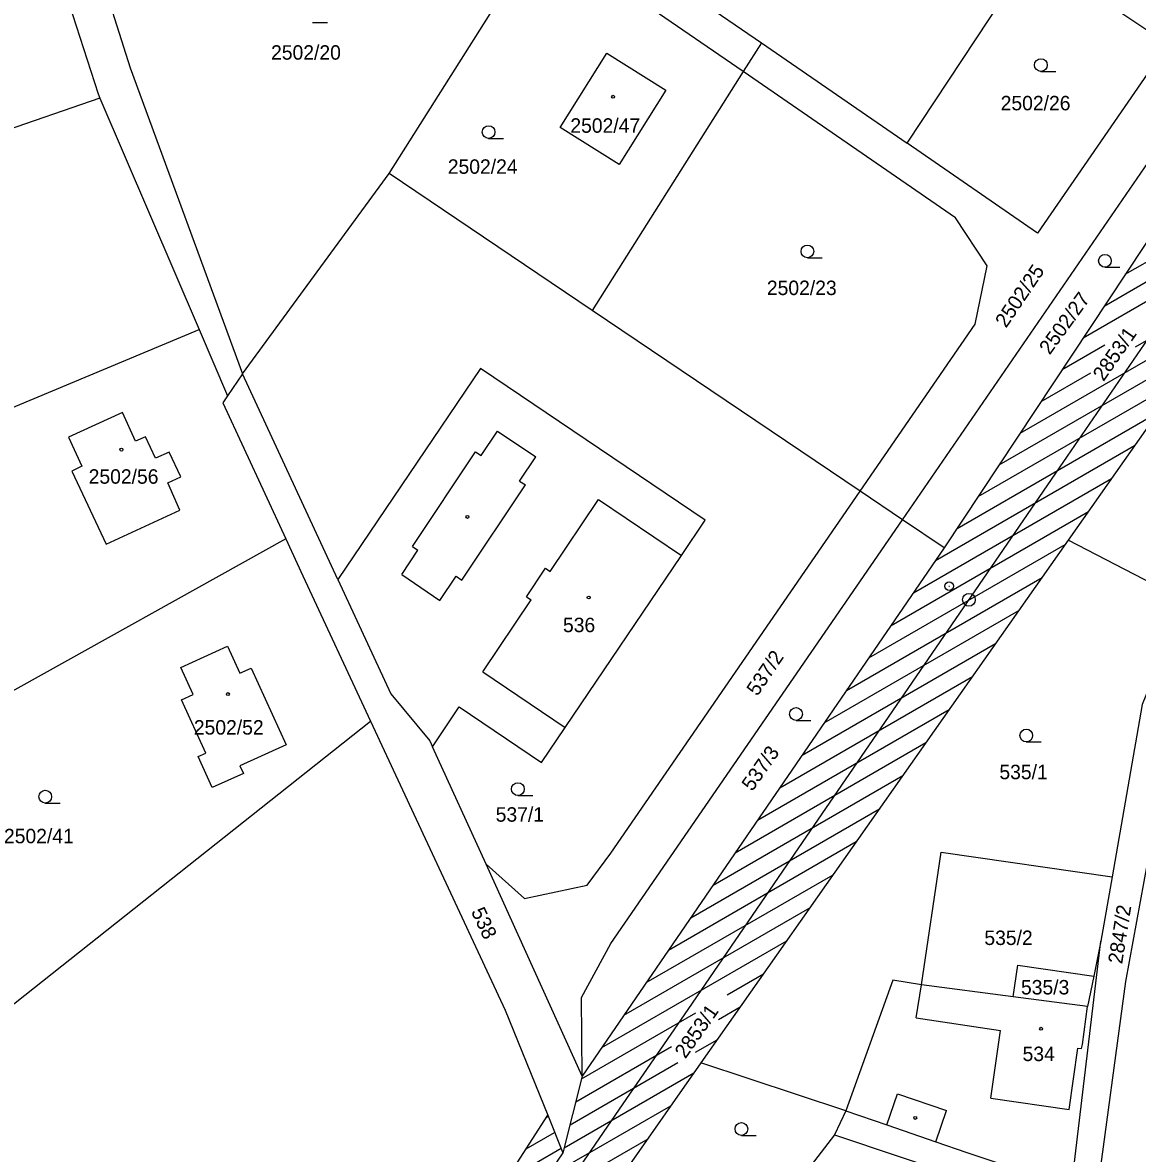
# Model space of a CAD drawing. Extents: x -558500 to -557517, y -1073973 to -1073051.
# Drawn here: x -558300.8 to -558169.6, y -1073540.5 to -1073407.4 of the extents above; entities that cross this region are included whole.
import ezdxf

# ---------------------------------------------------------------- set-up
doc = ezdxf.new("R2010")
doc.units = 0
for name, color, linetype in [('Hranice parcel', 7, 'Continuous'), ('Kolej', 7, 'Continuous'), ('Návěst místo trati', 7, 'Continuous'), ('Parcelní čísla', 7, 'Continuous'), ('Svazek obcí údolí Desné', 7, 'Continuous'), ('Vnitřní kresba', 7, 'Continuous'), ('Vrstva 1', 7, 'Continuous'), ('Značky budov', 7, 'Continuous'), ('Značky kultur', 7, 'Continuous')]:
    doc.layers.add(name, color=color, linetype=linetype)

msp = doc.modelspace()

# ---------------------------------------------------------------- linework, layer by layer
at = {"layer": 'Hranice parcel'}
for p, q in [((-558294.64, -1073392.22), (-558288.18, -1073412.71)), ((-558237.63, -1073393.44), (-558213.88, -1073409.79)), ((-558257.7, -1073425.14), (-558239.77, -1073396.82)), ((-558216.02, -1073413.17), (-558239.77, -1073396.82)), ((-558196.71, -1073421.6), (-558181.99, -1073399.3)), ((-558166.05, -1073409.92), (-558177.33, -1073402.38)), ((-558213.88, -1073409.79), (-558216.02, -1073413.17)), ((-558213.88, -1073409.79), (-558196.71, -1073421.6)), ((-558288.18, -1073412.71), (-558274.97, -1073448.74)), ((-558216.02, -1073413.17), (-558233.8, -1073441.26)), ((-558197.28, -1073465.89), (-558161.06, -1073413.25)), ((-558291.74, -1073416.28), (-558326.19, -1073428.15)), ((-558291.74, -1073416.28), (-558280.07, -1073443.5)), ((-558274.97, -1073448.74), (-558257.7, -1073425.14)), ((-558233.8, -1073441.26), (-558257.7, -1073425.14)), ((-558202.26, -1073462.53), (-558233.8, -1073441.26)), ((-558351.92, -1073473.58), (-558280.07, -1073443.5)), ((-558280.07, -1073443.5), (-558276.72, -1073451.31)), ((-558274.97, -1073448.74), (-558276.72, -1073451.31)), ((-558263.73, -1073472.95), (-558274.97, -1073448.74)), ((-558197.28, -1073465.89), (-558202.26, -1073462.53)), ((-558192.36, -1073469.21), (-558197.28, -1073465.89)), ((-558269.87, -1073468.15), (-558339.52, -1073506.95)), ((-558164.08, -1073475.42), (-558177.75, -1073468.29)), ((-558325.69, -1073541.72), (-558259.89, -1073489.61)), ((-558246.29, -1073506.44), (-558252.58, -1073492.61)), ((-558234.96, -1073531.36), (-558246.29, -1073506.44)), ((-558172.6, -1073507.93), (-558173.92, -1073515.47)), ((-558177.37, -1073544.49), (-558173.92, -1073515.47)), ((-558173.92, -1073515.47), (-558174.76, -1073519.59)), ((-558184.24, -1073522.04), (-558195.03, -1073520.62)), ((-558234.96, -1073531.36), (-558235.03, -1073522.1)), ((-558203.93, -1073535.45), (-558220.99, -1073529.81))]:
    msp.add_line(p, q, dxfattribs=at)
for points in [[(-558301.02, -1073387.75), (-558291.95, -1073415.8), (-558291.74, -1073416.28)], [(-558166.05, -1073409.92), (-558181.36, -1073432.16), (-558196.71, -1073421.6)], [(-558232.07, -1073410.99), (-558225.13, -1073415.34), (-558230.62, -1073424.08), (-558237.55, -1073419.73), (-558232.07, -1073410.99)], [(-558202.26, -1073462.53), (-558188.73, -1073442.87), (-558187.31, -1073436.01), (-558191.04, -1073430.36), (-558216.02, -1073413.17)], [(-558252.58, -1073492.61), (-558249.44, -1073487.92), (-558239.75, -1073494.46), (-558236.97, -1073490.34), (-558223.28, -1073470.09), (-558220.49, -1073465.96), (-558246.94, -1073448.09), (-558263.73, -1073472.95)], [(-558276.72, -1073451.31), (-558277.28, -1073452.14), (-558269.87, -1073468.15)], [(-558287.54, -1073456.66), (-558289.07, -1073453.28), (-558295.45, -1073456.18), (-558293.85, -1073459.61), (-558295.04, -1073460.19), (-558290.99, -1073468.78), (-558282.34, -1073464.77), (-558283.75, -1073461.57), (-558282.21, -1073460.84), (-558283.59, -1073457.95), (-558285.18, -1073458.67), (-558286.36, -1073456.15), (-558287.54, -1073456.66)], [(-558246.29, -1073506.44), (-558241.75, -1073510.46), (-558234.37, -1073508.88), (-558231.59, -1073505.15), (-558202.26, -1073462.53)], [(-558235.03, -1073522.1), (-558231.61, -1073515.78), (-558197.28, -1073465.89)], [(-558269.87, -1073468.15), (-558267.87, -1073472.49), (-558259.89, -1073489.61)], [(-558263.73, -1073472.95), (-558257.48, -1073486.4), (-558252.9, -1073491.92), (-558252.58, -1073492.61)], [(-558164.08, -1073475.42), (-558169.06, -1073487.65), (-558172.6, -1073507.93)], [(-558280.17, -1073493.77), (-558279.26, -1073493.36), (-558282.12, -1073487.08), (-558280.77, -1073486.48), (-558282.2, -1073483.29), (-558276.72, -1073480.79), (-558275.28, -1073483.95), (-558273.92, -1073483.36), (-558269.81, -1073492.38), (-558275.26, -1073494.86), (-558274.85, -1073495.76), (-558278.51, -1073497.42), (-558280.17, -1073493.77)], [(-558259.89, -1073489.61), (-558244.04, -1073523.6), (-558239.03, -1073535.96)], [(-558165.84, -1073492.01), (-558171, -1073520.22), (-558174.43, -1073545.49)], [(-558195.03, -1073520.62), (-558192.73, -1073505.02), (-558172.6, -1073507.93)], [(-558184.24, -1073522.04), (-558183.68, -1073518.31), (-558174.76, -1073519.59)], [(-558174.76, -1073519.59), (-558175.5, -1073523.19), (-558184.24, -1073522.04)], [(-558195.03, -1073520.62), (-558198.39, -1073520.09), (-558203.93, -1073535.45)], [(-558203.93, -1073535.45), (-558205.25, -1073538.29), (-558208.03, -1073541.86), (-558210.44, -1073548.45), (-558210.55, -1073548.74)], [(-558203.93, -1073535.45), (-558199.11, -1073537.11), (-558193.35, -1073539.1), (-558189.69, -1073540.36), (-558187.24, -1073541.19), (-558177.37, -1073544.49)]]:
    msp.add_lwpolyline(points, dxfattribs=at)
at = {"layer": 'Kolej'}
for points in [[(-558222.5, -1073523.52), (-558211.35, -1073507.26), (-558189.16, -1073474.89), (-558177.86, -1073458.42), (-558166.63, -1073442.09)], [(-558235.71, -1073542.74), (-558232.47, -1073538.02), (-558229.71, -1073534.01), (-558222.5, -1073523.52)]]:
    msp.add_lwpolyline(points, dxfattribs=at)
at = {"layer": 'Návěst místo trati'}
msp.add_line((-558191.83, -1073473.72), (-558191.73, -1073473.72), dxfattribs=at)
for centre, radius in [((-558191.78, -1073473.72), 0.5), ((-558189.45, -1073475.32), 0.75)]:
    msp.add_circle(centre, radius, dxfattribs=at)
at = {"layer": 'Svazek obcí údolí Desné'}
for p, q in [((-558138.47, -1073412.32), (-558177.75, -1073468.29)), ((-558157.08, -1073415.91), (-558192.36, -1073469.21)), ((-558171.05, -1073437.02), (-558145.41, -1073422.21)), ((-558173.52, -1073440.75), (-558148.14, -1073426.1)), ((-558176, -1073444.49), (-558150.86, -1073429.98)), ((-558169.85, -1073445.56), (-558156.31, -1073437.74)), ((-558183.42, -1073455.7), (-558159.04, -1073441.63)), ((-558185.89, -1073459.44), (-558161.76, -1073445.51)), ((-558178.47, -1073448.23), (-558173.43, -1073445.32)), ((-558180.95, -1073451.97), (-558175.11, -1073448.6)), ((-558188.37, -1073463.18), (-558164.49, -1073449.39)), ((-558190.84, -1073466.92), (-558167.21, -1073453.27)), ((-558193.37, -1073470.69), (-558169.94, -1073457.16)), ((-558195.99, -1073474.51), (-558172.66, -1073461.04)), ((-558198.61, -1073478.33), (-558175.39, -1073464.92)), ((-558177.75, -1073468.29), (-558220.99, -1073529.81)), ((-558201.23, -1073482.15), (-558178.11, -1073468.81)), ((-558192.36, -1073469.21), (-558234.96, -1073531.36)), ((-558203.85, -1073485.98), (-558180.84, -1073472.69)), ((-558206.47, -1073489.8), (-558183.58, -1073476.58)), ((-558209.09, -1073493.62), (-558186.31, -1073480.47)), ((-558211.71, -1073497.44), (-558189.04, -1073484.35)), ((-558214.33, -1073501.26), (-558191.77, -1073488.24)), ((-558216.95, -1073505.08), (-558194.5, -1073492.12)), ((-558219.57, -1073508.91), (-558197.23, -1073496.01)), ((-558222.19, -1073512.73), (-558199.97, -1073499.9)), ((-558224.81, -1073516.55), (-558202.7, -1073503.78)), ((-558227.43, -1073520.37), (-558205.43, -1073507.67)), ((-558230.05, -1073524.19), (-558208.16, -1073511.56)), ((-558232.67, -1073528.02), (-558210.89, -1073515.44)), ((-558217.9, -1073521.8), (-558213.62, -1073519.33)), ((-558218.92, -1073524.7), (-558216.36, -1073523.22)), ((-558235.04, -1073531.7), (-558221.61, -1073523.94)), ((-558221.63, -1073528.57), (-558219.09, -1073527.1)), ((-558235.72, -1073534.4), (-558224.45, -1073527.89)), ((-558236.4, -1073537.1), (-558223.71, -1073529.77)), ((-558220.99, -1073529.81), (-558229.66, -1073542.22)), ((-558234.96, -1073531.36), (-558237.23, -1073540.41)), ((-558237.08, -1073539.8), (-558221.81, -1073530.99)), ((-558239.23, -1073543.35), (-558224.52, -1073534.86)), ((-558239.23, -1073536.26), (-558238.97, -1073536.11)), ((-558239.03, -1073535.96), (-558237.23, -1073540.41)), ((-558241.58, -1073539.93), (-558238.21, -1073537.99)), ((-558241.81, -1073547.15), (-558227.22, -1073538.73)), ((-558243.94, -1073543.61), (-558237.45, -1073539.86))]:
    msp.add_line(p, q, dxfattribs=at)
for points in [[(-558286.79, -1073633.11), (-558279.73, -1073611.9), (-558267.63, -1073584.34), (-558254.51, -1073560.06), (-558239.03, -1073535.96)], [(-558237.23, -1073540.41), (-558250.35, -1073559.71), (-558264.4, -1073584.99), (-558277.08, -1073613.49), (-558283.33, -1073632.3), (-558290.3, -1073658.29), (-558296.01, -1073700.28), (-558297.13, -1073716.84), (-558297.21, -1073758.56)]]:
    msp.add_lwpolyline(points, dxfattribs=at)
at = {"layer": 'Vnitřní kresba'}
for p, q in [((-558246.86, -1073458.35), (-558244.94, -1073455.47)), ((-558244.94, -1073455.47), (-558240.43, -1073458.48)), ((-558254.96, -1073469.03), (-558247.53, -1073457.9)), ((-558247.53, -1073457.9), (-558246.86, -1073458.35)), ((-558242.35, -1073461.35), (-558240.43, -1073458.48)), ((-558249.13, -1073472.99), (-558241.66, -1073461.81)), ((-558242.35, -1073461.35), (-558241.66, -1073461.81)), ((-558238.73, -1073471.97), (-558233.06, -1073463.5)), ((-558233.06, -1073463.5), (-558223.28, -1073470.09)), ((-558254.96, -1073469.03), (-558254.3, -1073469.47)), ((-558256.21, -1073472.34), (-558254.3, -1073469.47)), ((-558241.52, -1073474.97), (-558239.27, -1073471.61)), ((-558239.27, -1073471.61), (-558238.73, -1073471.97)), ((-558256.21, -1073472.34), (-558251.73, -1073475.41)), ((-558251.73, -1073475.41), (-558249.81, -1073472.53)), ((-558249.81, -1073472.53), (-558249.13, -1073472.99)), ((-558246.65, -1073483.79), (-558240.98, -1073475.33)), ((-558241.52, -1073474.97), (-558240.98, -1073475.33)), ((-558246.65, -1073483.79), (-558236.97, -1073490.34)), ((-558195.64, -1073524.53), (-558195.03, -1073520.62)), ((-558176.08, -1073527.66), (-558175.5, -1073523.19)), ((-558195.64, -1073524.53), (-558185.73, -1073525.99)), ((-558186.85, -1073533.98), (-558185.73, -1073525.99)), ((-558177.65, -1073535.29), (-558176.63, -1073528.09)), ((-558176.63, -1073528.09), (-558176.18, -1073528.11)), ((-558176.18, -1073528.11), (-558176.08, -1073527.66)), ((-558199.11, -1073537.11), (-558197.85, -1073533.46)), ((-558197.85, -1073533.46), (-558192.08, -1073535.4)), ((-558186.85, -1073533.98), (-558177.65, -1073535.29)), ((-558193.35, -1073539.1), (-558192.08, -1073535.4)), ((-558205.25, -1073538.29), (-558189.93, -1073543.4))]:
    msp.add_line(p, q, dxfattribs=at)
at = {"layer": 'Značky budov'}
for centre in [(-558231.33, -1073416.12), (-558289.2, -1073457.65), (-558248.48, -1073465.56), (-558234.2, -1073475.05), (-558276.67, -1073486.42), (-558180.95, -1073525.8), (-558195.77, -1073536.28)]:
    msp.add_circle(centre, 0.175, dxfattribs=at)
at = {"layer": 'Značky kultur'}
for p, q in [((-558266.71, -1073407.4), (-558264.96, -1073407.4)), ((-558180.98, -1073413.15), (-558179.23, -1073413.15)), ((-558245.99, -1073421.03), (-558244.24, -1073421.03)), ((-558208.46, -1073435.07), (-558206.71, -1073435.07)), ((-558173.44, -1073436.18), (-558171.69, -1073436.18)), ((-558209.8, -1073489.51), (-558208.05, -1073489.51)), ((-558182.7, -1073492.04), (-558180.95, -1073492.04)), ((-558242.54, -1073498.35), (-558240.79, -1073498.35)), ((-558298.17, -1073499.24), (-558296.42, -1073499.24)), ((-558216.23, -1073538.34), (-558214.48, -1073538.34))]:
    msp.add_line(p, q, dxfattribs=at)
for centre in [(-558180.98, -1073412.4), (-558245.99, -1073420.28), (-558208.46, -1073434.32), (-558173.44, -1073435.43), (-558209.8, -1073488.76), (-558182.7, -1073491.29), (-558242.54, -1073497.6), (-558298.17, -1073498.49), (-558216.23, -1073537.59)]:
    msp.add_circle(centre, 0.75, dxfattribs=at)

# ---------------------------------------------------------------- texts
at = {"layer": 'Parcelní čísla'}
for s, p in [('2502/20', (-558271.59, -1073411.76)), ('2502/26', (-558185.71, -1073417.72)), ('2502/47', (-558236.36, -1073420.36)), ('2502/24', (-558250.79, -1073425.19)), ('2502/23', (-558213.23, -1073439.46)), ('2502/56', (-558293.06, -1073461.66)), ('536', (-558237.23, -1073479.13)), ('2502/52', (-558280.68, -1073491.18)), ('535/1', (-558185.86, -1073496.43)), ('537/1', (-558245.15, -1073501.43)), ('2502/41', (-558303.03, -1073503.97)), ('535/2', (-558187.63, -1073515.94)), ('535/3', (-558183.32, -1073521.76)), ('534', (-558183.13, -1073529.6))]:
    msp.add_text(s, height=1.7, dxfattribs=at).set_placement(p)
for s, rotation, p in [('2502/25', 56, (-558185.07, -1073443.42)), ('2502/27', 54, (-558179.94, -1073446.58)), ('537/2', 56, (-558214.34, -1073486.74)), ('537/3', 55, (-558214.94, -1073497.94)), ('538', 295, (-558248.08, -1073512)), ('2847/2', 81, (-558171.41, -1073518.24))]:
    msp.add_text(s, height=1.7, rotation=rotation, dxfattribs=at).set_placement(p)
at = {"layer": 'Vrstva 1'}
for p in [(-558173.6, -1073449.7), (-558222.82, -1073529.41)]:
    msp.add_text('2853/1', height=1.7, rotation=55, dxfattribs=at).set_placement(p)

doc.saveas('drawing.dxf')
